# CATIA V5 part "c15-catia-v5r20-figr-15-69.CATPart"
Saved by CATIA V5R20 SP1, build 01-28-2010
Part number: Part1
Bounding box of the stored display mesh (mm): x -59.264 to 75.079, y -54.323 to 58.486, z 0 to 41.762
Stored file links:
  D:\v5_r20\psrt_files_downloaded\c15\c15-catia-v5r20-figr-15-69.CATPart
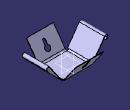
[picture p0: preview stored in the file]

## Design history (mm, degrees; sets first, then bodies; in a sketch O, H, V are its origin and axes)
SheetMetalParameters1: Thickness 1, BendRadius 5, KFactor 0.5 {= log(min(100,max(20*SheetMetalParameters1.BendRadius,SheetMetalParameters1.Thickness)/SheetMetalParameters1.Thickness))/log(100)/2}, ReliefRadialLength 1, ReliefAxialLength 2, MinimumBendRadius 0
Body1 (main body)
  Sketch1 on xy-plane, origin (0, 0, 0), H (1, 0, 0), V (0, 1, 0)
    line L1 (-24.5181, 30.1968) -> (40.3332, 30.1968)
    line L2 (40.3332, 30.1968) -> (40.3332, -26.0343)
    line L3 (40.3332, -26.0343) -> (-24.5181, -26.0343)
    line L4 (-24.5181, -26.0343) -> (-24.5181, 30.1968)
    horizontal: L1 H, L3 H
    vertical: L2 V, L4 V
  Wall1: Thickness 1, Profile Sketch1
  d_NewWallOnEdge1: NewWallOnEdge_Edge edge [face of Wall1 | face of Wall1], NewWallOnEdge_Length 40.2311, NewWallOnEdge_HeightLimitOffset 0, NewWallOnEdge_WidthOffset1 0, NewWallOnEdge_WidthOffset2 0, NewWallOnEdge_Angle 125, NewWallOnEdge_BendRadiusValue 5 {= SheetMetalParameters1.BendRadius}, NewWallOnEdge_BendTable SheetMetalParameters1, KFacteur 0.5 {= log(min(100,max(20*d_NewWallOnEdge1.Radius,SheetMetalParameters1.Thickness)/SheetMetalParameters1.Thickness))/log(100)/2}
  d_NewWallOnEdge2: NewWallOnEdge_Edge edge [face of Wall1 | face of Wall1], NewWallOnEdge_Length 40.2311, NewWallOnEdge_HeightLimitOffset 0, NewWallOnEdge_WidthOffset1 0, NewWallOnEdge_WidthOffset2 0, NewWallOnEdge_Angle 125, NewWallOnEdge_BendRadiusValue 5 {= SheetMetalParameters1.BendRadius}, NewWallOnEdge_BendTable SheetMetalParameters1, KFacteur 0.5 {= log(min(100,max(20*d_NewWallOnEdge2.Radius,SheetMetalParameters1.Thickness)/SheetMetalParameters1.Thickness))/log(100)/2}
  d_NewWallOnEdge3: NewWallOnEdge_Edge edge [face of Wall1 | face of Wall1], NewWallOnEdge_Length 40.2311, NewWallOnEdge_HeightLimitOffset 0, NewWallOnEdge_WidthOffset1 0, NewWallOnEdge_WidthOffset2 0, NewWallOnEdge_Angle 125, NewWallOnEdge_BendRadiusValue 5 {= SheetMetalParameters1.BendRadius}, NewWallOnEdge_BendTable SheetMetalParameters1, KFacteur 0.5 {= log(min(100,max(20*d_NewWallOnEdge3.Radius,SheetMetalParameters1.Thickness)/SheetMetalParameters1.Thickness))/log(100)/2}
  d_NewWallOnEdge4: NewWallOnEdge_Edge edge [face of Wall1 | face of Wall1], NewWallOnEdge_Length 40.2311, NewWallOnEdge_HeightLimitOffset 0, NewWallOnEdge_WidthOffset1 0, NewWallOnEdge_WidthOffset2 0, NewWallOnEdge_Angle 125, NewWallOnEdge_BendRadiusValue 5 {= SheetMetalParameters1.BendRadius}, NewWallOnEdge_BendTable SheetMetalParameters1, KFacteur 0.5 {= log(min(100,max(20*d_NewWallOnEdge4.Radius,SheetMetalParameters1.Thickness)/SheetMetalParameters1.Thickness))/log(100)/2}
  Sketch2 on face of d_NewWallOnEdge4, origin (0, -16.9994, -11.9031), H (-1, 0, 0), V (0, -0.5736, 0.8192)
    construction line L1 (-8.3417, 33.0355) -> (-8.3417, 47.6528)
    line L2 (-5.6402, 47.6528) -> (-5.6402, 38.4491)
    line L3 (-11.0431, 38.4491) -> (-11.0431, 47.6528)
    arc A1 centre (-8.3417, 33.0355) radius 6.0503 from (-5.6402, 38.4491) to (-11.0431, 38.4491) cw
    arc A2 centre (-8.3417, 47.6528) radius 2.7015 from (-11.0431, 47.6528) to (-5.6402, 47.6528) cw
    radius A1 = 6.0503
    radius A2 = 2.7015
    vertical: L1 V
    tangency: A2 L2, A2 L3
    parallelism: L2 L3, L2 L1
  CutOut1: Direction Sketch2, EndLimit through (limit type 3), Orientation false, Profile Sketch2, StartLimit through (limit type 2)
  Sketch3 on face of d_NewWallOnEdge2, origin (0, 19.7925, -13.8589), H (1, 0, 0), V (0, 0.5736, 0.8192)
    construction line L1 (6.0153, 41.1403) -> (6.0153, 57.8706)
    line L2 (8.7383, 57.8706) -> (8.7383, 46.3808)
    line L3 (3.2923, 46.3808) -> (3.2923, 57.8706)
    arc A1 centre (6.0153, 41.1403) radius 5.9058 from (8.7383, 46.3808) to (3.2923, 46.3808) cw
    arc A2 centre (6.0153, 57.8706) radius 2.723 from (3.2923, 57.8706) to (8.7383, 57.8706) cw
    radius A1 = 5.9058
    radius A2 = 2.723
    vertical: L1 V
    tangency: A2 L2, A2 L3
    parallelism: L2 L3, L2 L1
  CutOut2: Direction Sketch3, EndLimit through (limit type 3), Orientation true, Profile Sketch3, StartLimit through (limit type 2)
  Flange1: Angle 90, Length 5, Radius 3, KFacteur 0.444538 {= log(min(100,max(20*Flange1.Radius,SheetMetalParameters1.Thickness)/SheetMetalParameters1.Thickness))/log(100)/2}, Guide edge [face of d_NewWallOnEdge1 | face of d_NewWallOnEdge1]
  Flange2: Angle 90, Length 5, Radius 3, KFacteur 0.444538 {= log(min(100,max(20*Flange2.Radius,SheetMetalParameters1.Thickness)/SheetMetalParameters1.Thickness))/log(100)/2}, Guide edge [face of d_NewWallOnEdge3 | face of d_NewWallOnEdge3]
